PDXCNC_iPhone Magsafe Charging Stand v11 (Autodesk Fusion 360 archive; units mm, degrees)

design "iPhone Magsafe Charging Stand" references "Apple_MagSafe_Charger_2020"
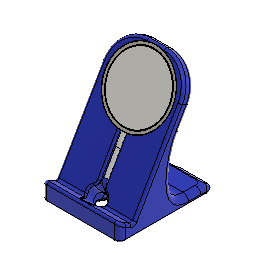
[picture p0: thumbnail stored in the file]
parameter "Angle" = 30 comment "Tilt Back Angle"
parameter "Shelf" = 13.335 comment "Projection of Bottom Resting Shelf"
parameter "HeightCenterMS" = 73.66 comment "MagSafe Height from Shelf toCenter of Magsafe"
parameter "CordSlot" = 5 comment "Width of Cord Slot"
parameter "BackThick" = 10
parameter "BaseThick" = 7
parameter "Width" = 65 comment "Overall Width"
parameter "BackTall" = 103 comment "Height of Back"
parameter "LgFillet" = 4.5
parameter "MFillet" = 2
parameter "SFillet" = 1.5
parameter "MagSafeOD" = 55.9
parameter "MagFitTol" = 0.2
parameter "USBSlotWidth" = 11.6 (= "10.6 mm + 1 mm")
parameter "USBSlotDepth" = 7.5 (= "6.5 mm + 1 mm")
external_derived "ExternalDerived1" bodies "Body1"
derived_instance "DerivedInstance1"
sketch "Section" plane through (0, 0, 0) normal (1, 0, 0) x axis (0, 1, 0)
  line L1 (56.5, 97.8609) -> (0, 0)
  line L2 (103.693, 0) -> (0, 0)
  line L3 (-6.5484, 15.3278) -> (5, 8.6603)
  line L4 (65.1603, 92.8609) -> (56.5, 97.8609)
  line L5 (75, 0) -> (0, 0)
  line L6 (65.51, 7) -> (75, 0)
  line L7 (50.51, 7) -> (65.51, 7)
  line L8 (43.7768, 55.8236) -> (65.1603, 92.8609)
  curve K1 (50.51, 7) -> (43.7768, 55.8236)
  line L9 (-6.5484, 0) -> (-6.5484, 15.3278)
  line L10 (-6.5484, 0) -> (0, 0)
  point P1 (0, 0)
  point P2 (0, 0)
  point P5 (5, 8.6603)
  point P8 (0, 0)
  point P9 (75, 0)
  point P6 (-6.5484, 15.3278)
  point P3 (56.5, 97.8609)
  point P7 (65.1603, 92.8609)
  point P10 (65.51, 7)
  point P12 (50.51, 7)
  horizontal L2
  coincident P1 P2
  coincident L1 P5
  perpendicular L1 L3
  perpendicular L1 L4
  coincident P1 P8
  coincident L2 P9
  horizontal L7
  perpendicular L4 L8
  vertical L9
  perpendicular L9 L10
  dimension "d4" angle L1 L2 = 60 (= "90 deg - Angle")
  dimension "d6" distance P5 P6 = 13.335 (= "Shelf")
  dimension "d8" distance P3 P7 = 10 (= "BackThick")
  dimension "d9" distance P8 P9 = 75
  dimension "d12" distance L2 P10 = 7 (= "BaseThick")
  dimension "d13" distance P10 P12 = 15
  dimension "d20" distance P3 L3 = 103 (= "BackTall")
  dimension "d21" distance P1 P5 = 10
  dimension "d74" distance P9 P10 = 9.49
extrude "Extrude1" new body sketch "Section" profile of L1 L3 L4 L5 L6 L7 L8 K1 L9 L10 distance 65 (= "Width")
sketch "Magnet" plane through (0, 0, 0) normal (0, -0.866, 0.5) x axis (1, 0, 0)
  line L1 (32.5, 10) -> (-32.5, 10)
  line L2 (32.5, 113) -> (32.5, 10)
  line L3 (-32.5, 113) -> (32.5, 113)
  line L4 (-32.5, 10) -> (-32.5, 113)
  line L5 (0, 113) -> (0, 10)
  line L6 (0, 10) -> (0, 55.61)
  line L7 (-2.5, 10) -> (-2.5, 55.7216)
  line L8 (2.5, 10) -> (2.5, 55.7216)
  circle C1 centre (0, 83.66) radius 28.05
  point P6 (0, 10)
  point P7 (0, 113)
  point P8 (0, 83.66)
  point P9 (0, 55.61)
  point P12 (2.5, 55.7216)
  point P13 (-2.5, 55.7216)
  midpoint L1 P6
  midpoint L3 P7
  coincident L5 P8
  coincident C1 P9
  coincident L5 P9
  coincident C1 P12
  coincident C1 P13
  dimension "d17" diameter C1 = 56.1 (= "MagSafeOD + MagFitTol")
  dimension "d18" distance L1 P8 = 73.66 (= "HeightCenterMS")
joint "Assemble1" alignAngle 0 alignOffsetX 0 alignOffsetY 0 alignOffsetZ 0
fillet "Fillet1" radius 4.5 (= "LgFillet") 2 (= "MFillet") 1.5 (= "SFillet") 25.4
sketch "Cord" plane through (0, 0, 0) normal (1, 0, 0) x axis (0, 1, 0)
  line L1 (55.5, 96.1288) -> (43.8, 75.8638)
  line L2 (6, 10.3923) -> (43.8, 75.8638)
  line L3 (43.8, 75.8638) -> (6, 10.3923)
  line L4 (55.5, 96.1288) -> (43.8, 75.8638)
  line L5 (65.3856, 0) -> (70.4395, 0)
  line L6 (65.3856, 0) -> (70.4395, 0)
  line L7 (-2.0484, 0) -> (65.3856, 0)
  line L8 (-5.0484, 0) -> (-2.0484, 0)
  line L9 (-5.0484, 0) -> (-2.0484, 0)
  line L10 (65.3856, 0) -> (-2.0484, 0)
  line L11 (8.5175, 14.7527) -> (16.4238, 28.4469)
  curve K1 (22.8412, 0) -> (8.5175, 14.7527)
  curve K2 (6.7423, 11.678) -> (10.2926, 17.8273)
  line L12 (22.8412, 0) -> (70.4395, 0)
  line L13 (25, 0) -> (25.2191, 0)
  line L14 (76.4397, 0) -> (22.8412, 0)
  line L15 (24.9, 43.1281) -> (16.4238, 28.4469)
  line L16 (13.5817, 17.9242) -> (34.8393, 54.7434)
  line L17 (56.5, 97.8609) -> (5, 8.6603)
  curve K3 (22.8412, 0) -> (13.5817, 17.9242)
  curve K4 (25.7064, 0) -> (19.976, 0)
  point P9 (16.4238, 28.4469)
  point P5 (70.4395, 0)
  point P10 (70.4395, 0)
  point P11 (25, 0)
  point P13 (8.5175, 14.7527)
  point P12 (25.2191, 0)
  point P14 (22.8412, 0)
  point P18 (24.9, 43.1281)
  point P23 (19.976, 0)
  coincident L3 P9
  parallel L3 L11
  coincident P5 P10
  coincident L7 P11
  parallel L7 L12
  coincident L3 P13
  coincident P12 L12
  coincident L7 P14
  coincident L2 P13
  midpoint P13 K2
  collinear L12 L13
  midpoint L3 P18
  parallel L3 L15
  parallel L16 L17
  midpoint P14 K4
  coincident L7 P23
  dimension "d47" distance L16 L17 = 2.8
pipe "Pipe1" SectionSize 5 (= "CordSlot") SectionThickness 1.27
extrude "Extrude2" cut sketch "Magnet" profile of C1 along a picked direction blind -5.5372 (= "-0.213 in - 0.005 in")
extrude "Extrude3" cut sketch "Magnet" profile of L1 C1 L7 L8 along a picked direction to an object
delete_face "DeleteFace1"
sketch "USB Slot" plane through (0, 0, 0) normal (0, 0, 1) x axis (1, 0, 0)
  line L1 (2.727, 9.982) -> (-2.727, 9.982)
  line L2 (-2.727, 17.482) -> (2.727, 17.482)
  line L3 (6.477, 13.732) -> (-6.477, 13.732)
  line L4 (-2.5, 6) -> (2.5, 6)
  line L5 (0, 6) -> (0, 21.4639)
  curve K1 (2.5, 23.5817) -> (-2.5, 23.5817)
  arc A1 centre (2.727, 13.732) radius 3.75 clockwise from (2.727, 17.482) to (2.727, 9.982)
  arc A2 centre (-2.727, 13.732) radius 3.75 clockwise from (-2.727, 9.982) to (-2.727, 17.482)
  point P8 (-6.477, 13.732)
  point P9 (6.477, 13.732)
  point P11 (0, 13.732)
  point P12 (0, 0)
  point P15 (0, 21.4639)
  point P16 (0, 6)
  tangent L1 A1
  tangent A1 L2
  parallel L1 L2
  tangent L2 A2
  tangent L1 A2
  midpoint A2 P8
  midpoint A1 P9
  horizontal L3
  midpoint L3 P11
  vertical P11 P12
  coincident P15 K1
  midpoint L4 P16
  perpendicular L4 L5
  midpoint P11 L5
  dimension "d57" diameter A1 = 7.5 (= "USBSlotDepth")
  dimension "d87" distance P9 P11 = 6.477
sketch "USB End Section" plane through (0, 0, 0) normal (1, 0, 0) x axis (0, 1, 0)
  line L1 (27.8608, 48.2563) -> (6, 10.3923)
  line L2 (55.5, 96.1288) -> (27.8608, 48.2563)
  line L3 (6, 10.3923) -> (27.8608, 48.2563)
  line L4 (43.8, 75.8638) -> (6, 10.3923)
  line L5 (55.5, 96.1288) -> (43.8, 75.8638)
  line L6 (55.5, 96.1288) -> (43.8, 75.8638)
  line L7 (6, 10.3923) -> (43.8, 75.8638)
  line L8 (70.4395, 0) -> (22.8412, 0)
  line L9 (15.8007, 0) -> (20, 0)
  line L10 (65.3856, 0) -> (70.4395, 0)
  line L11 (-2.0484, 0) -> (65.3856, 0)
  line L12 (-5.0484, 0) -> (-2.0484, 0)
  line L13 (-5.0484, 0) -> (-2.0484, 0)
  line L14 (65.3856, 0) -> (-2.0484, 0)
  line L15 (65.3856, 0) -> (70.4395, 0)
  line L16 (13.732, 2.0214) -> (13.732, 0)
  line L17 (12.4477, 5.367) -> (6.7513, 11.6935)
  line L18 (22.8412, 0) -> (20, 0)
  line L19 (22.8412, 0) -> (70.4395, 0)
  line L20 (20, 0) -> (22.8412, 0)
  line L21 (55.5, 96.1288) -> (27.8608, 48.2563)
  line L22 (-3.1476, 22.6874) -> (6.7513, 11.6935)
  arc A1 centre (8.732, 2.0214) radius 5 clockwise from (12.4477, 5.367) to (13.732, 2.0214)
  point P13 (13.732, 0)
  point P16 (13.732, 0)
  point P17 (6.7513, 11.6935)
  coincident P13 P16
  perpendicular L14 L16
  tangent L17 A1
  tangent L16 A1
  coincident L4 P17
  collinear L17 L22
  dimension "d58" radius A1 = 5
  dimension "d75" angle L16 L17 = 138
sweep "Sweep1" sketch "USB Slot" TwistAngle 0 TaperAngle 6.5
work_plane "WorkPlane1" AlongDistance 20.0025
sketch "Sketch6" plane through (0, 20.0025, 0) normal (0, 1, 0) x axis (1, 0, 0)
  arc A1 centre (0, 0) radius 2.5 clockwise from (2.5, 0) to (-2.5, 0)
  circle C1 centre (0, 0) radius 2.5
  circle C2 centre (0, -0.7281) radius 3.75
  point P2 (-2.5, 0)
  concentric A1 C1
  coincident P2 C1
  dimension "d76" diameter C2 = 7.5 (= "CordSlot * 1.5")
extrude "Extrude4" cut sketch "Sketch6" against normal blind 4.9501 taper 23
extrude "Extrude5" cut sketch "Sketch6" along normal blind 68.072 taper 0.25
delete_face "DeleteFace4"
fillet "Fillet4" radius 3.175 5.08 5.08
fillet "Fillet5" radius 1.5 (= "SFillet") 1.27
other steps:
derived_base_feature "Derived Base Feature" bodies "Body1"
pipe "Pipe1" SectionSize 5 (= "CordSlot") SectionThickness 1.27
create_component "CreateComponent1"
create_component "CreateComponent2"
joint_origin "JointOrigin1"
joint_origin "JointOrigin1"
named bodies: "Body1"

design "Apple_MagSafe_Charger_2020"
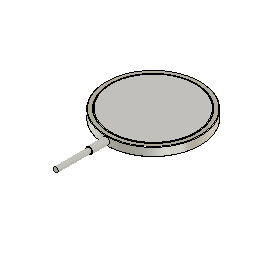
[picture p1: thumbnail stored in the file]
